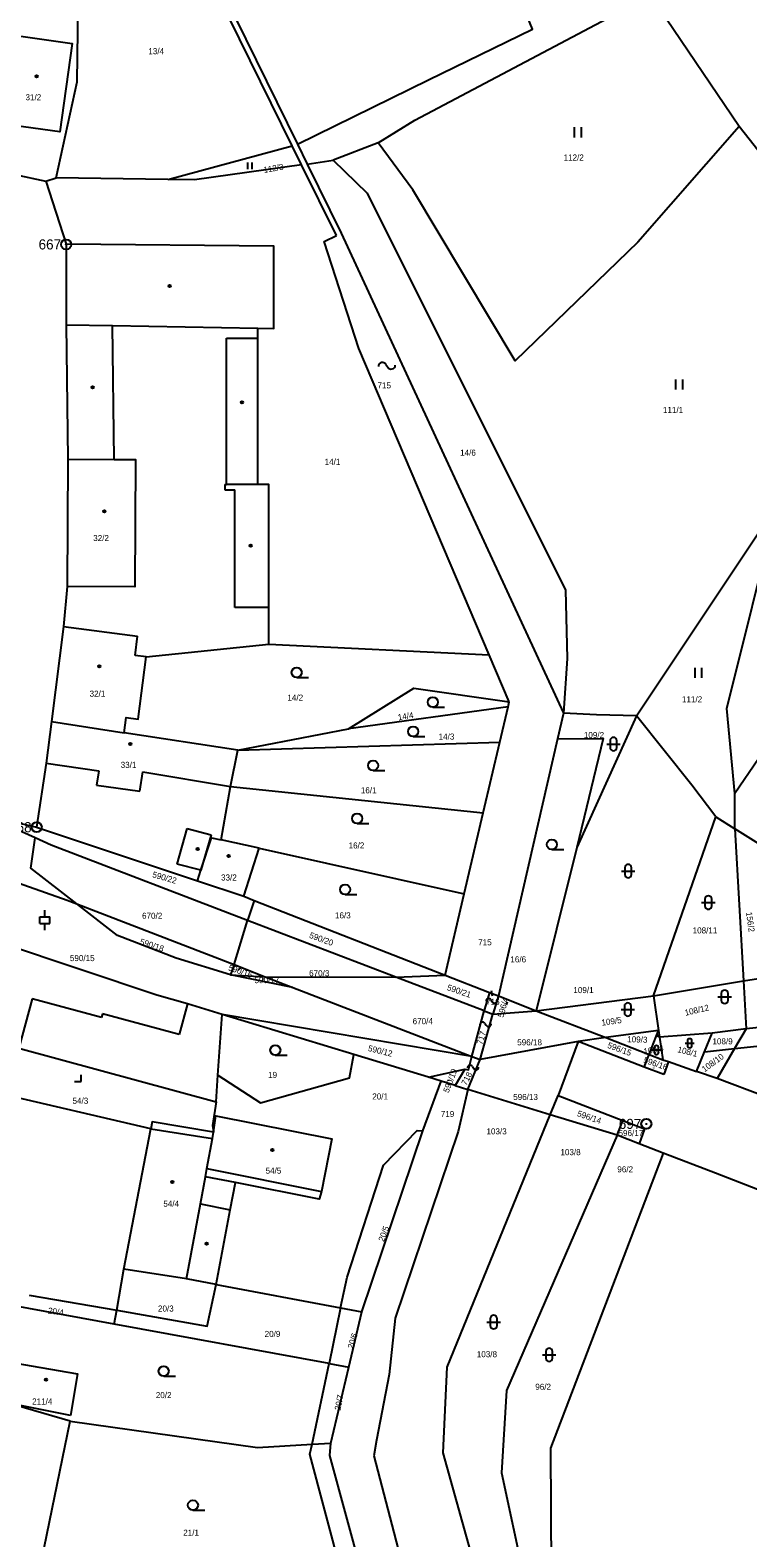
# Model space of a CAD drawing. Extents: x -758582 to -751794, y -998770 to -994350.
# Drawn here: x -755540.5 to -755433.6, y -995731.7 to -995507.3 of the extents above; entities that cross this region are included whole.
import ezdxf

# ---------------------------------------------------------------- set-up
doc = ezdxf.new("R2010")
doc.units = 0
for name, color, linetype in [('Hranice parcel', 7, 'Continuous'), ('Parcelní čísla', 7, 'Continuous'), ('Pop  PČ popisy', 7, 'Continuous'), ('Vnitřní kresba', 7, 'Continuous'), ('Značky bodu BP', 7, 'Continuous'), ('Značky budov', 7, 'Continuous'), ('Značky kultur', 7, 'Continuous')]:
    doc.layers.add(name, color=color, linetype=linetype)

msp = doc.modelspace()

# ---------------------------------------------------------------- linework, layer by layer
at = {"layer": 'Hranice parcel'}
for p, q in [((-755501.46, -995524.47), (-755518.41, -995490.01)), ((-755434.91, -995521.6), (-755447.94, -995502.32)), ((-755430.66, -995526.98), (-755434.91, -995521.6)), ((-755519.99, -995529.5), (-755501.46, -995524.47)), ((-755500.07, -995527.3), (-755501.46, -995524.47)), ((-755500.67, -995524.25), (-755499.23, -995527.18)), ((-755488.68, -995524.04), (-755495.36, -995526.63)), ((-755499.23, -995527.18), (-755495.36, -995526.63)), ((-755538.15, -995529.74), (-755536.58, -995529.23)), ((-755519.99, -995529.5), (-755536.58, -995529.23)), ((-755494.89, -995537.82), (-755500.07, -995527.3)), ((-755538.15, -995529.74), (-755535.12, -995539.1)), ((-755472.14, -995600.24), (-755491.55, -995554.63)), ((-755534.87, -995571.14), (-755534.97, -995590.08)), ((-755450.23, -995609.32), (-755429.18, -995577.78)), ((-755504.96, -995598.65), (-755472.14, -995600.24)), ((-755469.15, -995607.26), (-755472.14, -995600.24)), ((-755469.32, -995607.98), (-755469.15, -995607.26)), ((-755425.48, -995606.03), (-755435.57, -995620.9)), ((-755469.32, -995607.98), (-755493.08, -995611.28)), ((-755470.55, -995613.23), (-755469.32, -995607.98)), ((-755461.08, -995608.92), (-755461.96, -995612.75)), ((-755450.23, -995609.32), (-755459.08, -995628.93)), ((-755537.31, -995610.19), (-755526.49, -995611.85)), ((-755509.55, -995614.46), (-755526.49, -995611.85)), ((-755509.55, -995614.46), (-755493.08, -995611.28)), ((-755510.63, -995619.85), (-755509.55, -995614.46)), ((-755509.55, -995614.46), (-755470.55, -995613.23)), ((-755473.03, -995623.77), (-755470.55, -995613.23)), ((-755461.96, -995612.75), (-755470.78, -995651.03)), ((-755512.06, -995627.78), (-755510.63, -995619.85)), ((-755510.63, -995619.85), (-755473.03, -995623.77)), ((-755435.56, -995626.14), (-755435.57, -995620.9)), ((-755544.18, -995624.82), (-755539.51, -995625.91)), ((-755539.74, -995627.52), (-755543.7, -995625.72)), ((-755475.87, -995635.85), (-755473.03, -995623.77)), ((-755447.69, -995651.02), (-755438.4, -995624.35)), ((-755438.4, -995624.35), (-755435.56, -995626.14)), ((-755537.36, -995628.6), (-755539.74, -995627.52)), ((-755539.51, -995625.91), (-755515.56, -995633.91)), ((-755506.38, -995629.05), (-755512.06, -995627.78)), ((-755431.61, -995628.62), (-755435.56, -995626.14)), ((-755435.56, -995626.14), (-755434.3, -995648.77)), ((-755508.1, -995639.79), (-755537.36, -995628.6)), ((-755508.69, -995636.2), (-755506.38, -995629.05)), ((-755506.38, -995629.05), (-755475.87, -995635.85)), ((-755459.08, -995628.93), (-755465.13, -995653.23)), ((-755515.56, -995633.91), (-755508.69, -995636.2)), ((-755508.69, -995636.2), (-755507.13, -995636.81)), ((-755507.13, -995636.81), (-755508.1, -995639.79)), ((-755507.13, -995636.81), (-755478.71, -995647.93)), ((-755478.71, -995647.93), (-755475.87, -995635.85)), ((-755533.53, -995637.33), (-755510.13, -995646.37)), ((-755510.13, -995646.37), (-755508.1, -995639.79)), ((-755486.03, -995648.23), (-755508.1, -995639.79)), ((-755510.13, -995646.37), (-755510.66, -995647.89)), ((-755501.38, -995649.76), (-755510.66, -995647.89)), ((-755510.66, -995647.89), (-755505.48, -995648.17)), ((-755510.13, -995646.37), (-755505.48, -995648.17)), ((-755505.48, -995648.17), (-755486.03, -995648.23)), ((-755505.48, -995648.17), (-755501.38, -995649.76)), ((-755486.03, -995648.23), (-755478.71, -995647.93)), ((-755478.71, -995647.93), (-755472.12, -995650.51)), ((-755434.3, -995648.77), (-755426.44, -995647.6)), ((-755501.38, -995649.76), (-755474.71, -995660.06)), ((-755472.91, -995653.25), (-755486.03, -995648.23)), ((-755447.69, -995651.02), (-755434.3, -995648.77)), ((-755434.3, -995648.77), (-755433.9, -995655.95)), ((-755472.12, -995650.51), (-755470.78, -995651.03)), ((-755470.78, -995651.03), (-755471.61, -995653.75)), ((-755470.78, -995651.03), (-755465.13, -995653.23)), ((-755465.13, -995653.23), (-755447.69, -995651.02)), ((-755447.69, -995651.02), (-755446.93, -995656.16)), ((-755512.52, -995662.81), (-755511.87, -995653.79)), ((-755474.71, -995660.06), (-755511.87, -995653.79)), ((-755492.3, -995659.75), (-755511.87, -995653.79)), ((-755474.71, -995660.06), (-755472.91, -995653.25)), ((-755473.51, -995660.52), (-755471.61, -995653.75)), ((-755472.91, -995653.25), (-755471.61, -995653.75)), ((-755471.61, -995653.75), (-755465.13, -995653.23)), ((-755465.13, -995653.23), (-755454.79, -995657.23)), ((-755446.93, -995656.16), (-755454.79, -995657.23)), ((-755448.31, -995659.74), (-755446.93, -995656.16)), ((-755446.93, -995656.16), (-755446.78, -995657.19)), ((-755438.97, -995656.57), (-755446.78, -995657.19)), ((-755440.11, -995659.36), (-755438.97, -995656.57)), ((-755433.9, -995655.95), (-755438.97, -995656.57)), ((-755433.9, -995655.95), (-755435.62, -995658.88)), ((-755426.31, -995655.13), (-755433.9, -995655.95)), ((-755458.92, -995657.8), (-755473.51, -995660.52)), ((-755458.92, -995657.8), (-755461.9, -995665.86)), ((-755454.79, -995657.23), (-755458.92, -995657.8)), ((-755449.06, -995661.62), (-755458.92, -995657.8)), ((-755454.79, -995657.23), (-755448.31, -995659.74)), ((-755446.78, -995657.19), (-755446.28, -995660.53)), ((-755441.29, -995662.26), (-755440.11, -995659.36)), ((-755440.11, -995659.36), (-755435.62, -995658.88)), ((-755435.62, -995658.88), (-755438.23, -995663.32)), ((-755435.62, -995658.88), (-755427.59, -995658.02)), ((-755481.18, -995663.13), (-755492.3, -995659.75)), ((-755475.3, -995664.98), (-755473.51, -995660.52)), ((-755474.71, -995660.06), (-755473.51, -995660.52)), ((-755449.06, -995661.62), (-755448.31, -995659.74)), ((-755446.15, -995662.74), (-755449.06, -995661.62)), ((-755448.31, -995659.74), (-755446.28, -995660.53)), ((-755446.28, -995660.53), (-755445.47, -995660.81)), ((-755445.47, -995660.81), (-755446.15, -995662.74)), ((-755445.47, -995660.81), (-755441.29, -995662.26)), ((-755512.8, -995666.79), (-755512.52, -995662.81)), ((-755482.01, -995671.1), (-755479.31, -995663.72)), ((-755481.18, -995663.13), (-755475.78, -995661.92)), ((-755479.31, -995663.72), (-755481.18, -995663.13)), ((-755477.21, -995664.38), (-755479.31, -995663.72)), ((-755475.78, -995661.92), (-755477.21, -995664.38)), ((-755438.23, -995663.32), (-755441.29, -995662.26)), ((-755431.12, -995666), (-755438.23, -995663.32)), ((-755522.53, -995670.82), (-755550.45, -995664.32)), ((-755477.21, -995664.38), (-755475.3, -995664.98)), ((-755463.07, -995668.72), (-755475.3, -995664.98)), ((-755463.07, -995668.72), (-755461.9, -995665.86)), ((-755461.9, -995665.86), (-755452.23, -995669.59)), ((-755453.09, -995671.77), (-755463.07, -995668.72)), ((-755453.09, -995671.77), (-755452.23, -995669.59)), ((-755526.51, -995691.69), (-755522.53, -995670.82)), ((-755491.12, -995698.07), (-755482.01, -995671.1)), ((-755449.8, -995673.04), (-755453.09, -995671.77)), ((-755446.24, -995674.42), (-755449.8, -995673.04)), ((-755493.3, -995692.92), (-755487.9, -995676.22)), ((-755510.7, -995682.9), (-755509.93, -995678.82)), ((-755512.79, -995693.99), (-755510.7, -995682.9)), ((-755527.59, -995697.79), (-755526.51, -995691.69)), ((-755494.26, -995697.48), (-755493.3, -995692.92)), ((-755512.79, -995693.99), (-755494.26, -995697.48)), ((-755527.97, -995699.89), (-755547.25, -995696.36)), ((-755540.63, -995695.6), (-755527.59, -995697.79)), ((-755494.26, -995697.48), (-755495.99, -995705.74)), ((-755494.26, -995697.48), (-755491.12, -995698.07)), ((-755527.97, -995699.89), (-755527.59, -995697.79)), ((-755493.03, -995706.28), (-755491.12, -995698.07)), ((-755495.99, -995705.74), (-755527.97, -995699.89)), ((-755498.52, -995717.76), (-755495.99, -995705.74)), ((-755495.99, -995705.74), (-755493.03, -995706.28)), ((-755495.74, -995717.59), (-755493.03, -995706.28)), ((-755534.54, -995714.36), (-755543.92, -995711.63)), ((-755534.48, -995713.48), (-755543.92, -995711.63)), ((-755539.7, -995739.68), (-755534.54, -995714.36)), ((-755498.52, -995717.76), (-755495.74, -995717.59))]:
    msp.add_line(p, q, dxfattribs=at)
for points in [[(-755500.67, -995524.25), (-755481.17, -995514.65), (-755465.72, -995507.1), (-755477.43, -995478.45), (-755504.42, -995486.64)], [(-755516.07, -995489.69), (-755517.57, -995489.9), (-755500.67, -995524.25)], [(-755536.58, -995529.23), (-755533.47, -995514.96), (-755533.17, -995492.19)], [(-755488.68, -995524.04), (-755483.23, -995520.67), (-755454.56, -995505.52), (-755447.94, -995502.32)], [(-755542.58, -995508.06), (-755534.21, -995509.22), (-755536.04, -995522.4), (-755545.85, -995521.03), (-755544.4, -995510.63), (-755546.08, -995510.39), (-755545.83, -995508.61), (-755542.71, -995509.05), (-755542.58, -995508.06)], [(-755434.91, -995521.6), (-755450.04, -995538.83), (-755468.3, -995556.47), (-755483.49, -995531.04), (-755488.68, -995524.04)], [(-755560.21, -995523.57), (-755552.85, -995525.76), (-755542.78, -995528.76), (-755538.15, -995529.74)], [(-755495.36, -995526.63), (-755490.29, -995531.54), (-755460.76, -995590.63), (-755460.56, -995600.8), (-755461.08, -995608.92)], [(-755500.07, -995527.3), (-755516, -995529.56), (-755519.99, -995529.5)], [(-755499.23, -995527.18), (-755494.17, -995537.47), (-755461.08, -995608.92)], [(-755491.55, -995554.63), (-755496.69, -995538.71), (-755494.89, -995537.82)], [(-755535.12, -995539.1), (-755535.12, -995551.11), (-755534.87, -995571.14)], [(-755504.96, -995598.65), (-755504.96, -995593.2), (-755504.96, -995574.9), (-755506.56, -995574.9), (-755506.56, -995553.1), (-755506.56, -995551.63), (-755504.18, -995551.67), (-755504.19, -995539.4), (-755535.12, -995539.1)], [(-755534.87, -995571.14), (-755527.98, -995571.18), (-755524.8, -995571.19), (-755524.9, -995590.13), (-755534.97, -995590.08)], [(-755435.57, -995620.9), (-755436.79, -995608.25), (-755429.18, -995577.78)], [(-755534.97, -995590.08), (-755535.5, -995596.05), (-755537.31, -995610.19)], [(-755526.49, -995611.85), (-755526.19, -995609.59), (-755524.4, -995609.82), (-755523.22, -995600.54), (-755504.96, -995598.65)], [(-755493.08, -995611.28), (-755483.37, -995605.2), (-755469.15, -995607.26)], [(-755450.23, -995609.32), (-755456.19, -995609.2), (-755461.08, -995608.92)], [(-755438.4, -995624.35), (-755441.99, -995619.64), (-755450.23, -995609.32)], [(-755653.1, -995610.49), (-755646.26, -995612.32), (-755573.35, -995625.42), (-755559.76, -995628.44), (-755551.97, -995630.77), (-755534.97, -995636.78), (-755533.53, -995637.33)], [(-755537.31, -995610.19), (-755538.1, -995616.36), (-755539.51, -995625.91)], [(-755461.96, -995612.75), (-755455.2, -995612.71), (-755459.08, -995628.93)], [(-755533.53, -995637.33), (-755540.38, -995632.03), (-755539.74, -995627.52)], [(-755515.56, -995633.91), (-755515.05, -995632.33), (-755513.49, -995627.51), (-755512.06, -995627.78)], [(-755510.66, -995647.89), (-755518.75, -995645.43), (-755527.45, -995642.04), (-755533.53, -995637.33)], [(-755511.87, -995653.79), (-755517.07, -995652.21), (-755521.62, -995650.93), (-755544.6, -995643.22)], [(-755472.12, -995650.51), (-755472.85, -995653.01), (-755472.91, -995653.25)], [(-755548.51, -995657.09), (-755542.15, -995658.79), (-755512.8, -995666.79)], [(-755512.52, -995662.81), (-755506.19, -995666.96), (-755492.93, -995663.24), (-755492.3, -995659.75)], [(-755475.78, -995661.92), (-755475.23, -995662.04), (-755474.71, -995660.06)], [(-755475.3, -995664.98), (-755476.78, -995671.23), (-755486.16, -995699), (-755487.02, -995707.38), (-755488.91, -995717.17), (-755489.32, -995719.48)], [(-755512.8, -995666.79), (-755513.32, -995670.31), (-755513.16, -995671.3)], [(-755513.16, -995671.3), (-755522.33, -995669.76), (-755522.53, -995670.82)], [(-755513.16, -995671.3), (-755512.82, -995668.88), (-755495.58, -995672.33), (-755497.12, -995680.14), (-755497.43, -995681.29), (-755509.93, -995678.82)], [(-755468.42, -995763.84), (-755470.62, -995749.14), (-755478.99, -995719.07), (-755478.39, -995706.28), (-755463.07, -995668.72)], [(-755452.23, -995669.59), (-755449.02, -995670.83), (-755449.8, -995673.04)], [(-755514.16, -995676.73), (-755513.34, -995672.28), (-755513.16, -995671.3)], [(-755487.9, -995676.22), (-755482.85, -995671.08), (-755482.01, -995671.1)], [(-755453.09, -995671.77), (-755469.57, -995709.78), (-755470.33, -995722.02), (-755466.97, -995737.5)], [(-755446.24, -995674.42), (-755463.02, -995718.38), (-755462.93, -995736.73)], [(-755332.41, -995718.68), (-755438.45, -995677.43), (-755446.24, -995674.42)], [(-755509.93, -995678.82), (-755514.38, -995677.94), (-755514.16, -995676.73)], [(-755512.79, -995693.99), (-755517.19, -995693.17), (-755526.51, -995691.69)], [(-755527.59, -995697.79), (-755514.13, -995700.22), (-755512.79, -995693.99)], [(-755542.9, -995705.64), (-755533.45, -995707.3), (-755534.48, -995713.48)], [(-755534.54, -995714.36), (-755506.64, -995718.26), (-755498.52, -995717.76)], [(-755491.76, -995745.91), (-755498.83, -995719.23), (-755498.52, -995717.76)], [(-755488.58, -995746.23), (-755495.85, -995719.47), (-755495.74, -995717.59)], [(-755489.32, -995719.48), (-755477.02, -995766.71), (-755484.53, -995807.78), (-755498.8, -995841.6), (-755499.31, -995842.18)]]:
    msp.add_lwpolyline(points, dxfattribs=at)
at = {"layer": 'Pop  PČ popisy'}
for p, q in [((-755509.5, -995647.19), (-755509.22, -995646.9)), ((-755505.86, -995648.46), (-755505.82, -995648.58)), ((-755471.63, -995651.09), (-755471.78, -995650.26)), ((-755469.57, -995652.35), (-755469.4, -995651.9)), ((-755447.11, -995657.14), (-755446.79, -995656.68)), ((-755478.22, -995663.63), (-755478.22, -995663.69)), ((-755447.67, -995661.73), (-755447.7, -995661.78))]:
    msp.add_line(p, q, dxfattribs=at)
at = {"layer": 'Vnitřní kresba'}
for p, q in [((-755535.12, -995551.11), (-755528.23, -995551.24)), ((-755528.23, -995551.24), (-755506.56, -995551.63)), ((-755527.98, -995571.18), (-755528.23, -995551.24)), ((-755511.27, -995553.1), (-755506.56, -995553.1)), ((-755511.27, -995574.9), (-755511.27, -995553.1)), ((-755511.5, -995574.9), (-755511.5, -995575.7)), ((-755511.5, -995574.9), (-755511.27, -995574.9)), ((-755511.5, -995575.7), (-755510, -995575.7)), ((-755506.56, -995574.9), (-755511.27, -995574.9)), ((-755510, -995593.2), (-755510, -995575.7)), ((-755504.96, -995593.2), (-755510, -995593.2)), ((-755535.5, -995596.05), (-755524.49, -995597.46)), ((-755524.86, -995600.34), (-755524.49, -995597.46)), ((-755523.22, -995600.54), (-755524.86, -995600.34)), ((-755538.1, -995616.36), (-755530.27, -995617.5)), ((-755530.27, -995617.5), (-755530.6, -995619.63)), ((-755524.15, -995620.54), (-755523.68, -995617.65)), ((-755523.68, -995617.65), (-755510.63, -995619.85)), ((-755530.6, -995619.63), (-755524.15, -995620.54)), ((-755518.57, -995631.42), (-755517.1, -995626.09)), ((-755517.1, -995626.09), (-755513.55, -995627.04)), ((-755513.55, -995627.04), (-755515.05, -995632.33)), ((-755515.05, -995632.33), (-755518.57, -995631.42)), ((-755540.19, -995651.45), (-755542.15, -995658.79)), ((-755529.87, -995654.22), (-755540.19, -995651.45)), ((-755517.07, -995652.21), (-755518.28, -995656.75)), ((-755529.73, -995653.69), (-755529.87, -995654.22)), ((-755518.28, -995656.75), (-755529.73, -995653.69)), ((-755522.53, -995670.82), (-755513.34, -995672.28)), ((-755514.16, -995676.73), (-755497.12, -995680.14)), ((-755515.13, -995681.99), (-755514.38, -995677.94)), ((-755517.19, -995693.17), (-755515.13, -995681.99)), ((-755515.13, -995681.99), (-755510.7, -995682.9))]:
    msp.add_line(p, q, dxfattribs=at)
at = {"layer": 'Značky bodu BP'}
for centre, radius in [((-755535.12, -995539.15), 0.75), ((-755535.12, -995539.15), 0.03), ((-755539.51, -995625.91), 0.75), ((-755539.51, -995625.91), 0.03), ((-755448.75, -995670.08), 0.75), ((-755448.75, -995670.08), 0.03)]:
    msp.add_circle(centre, radius, dxfattribs=at)
at = {"layer": 'Značky budov'}
for p, q in [((-755487.53, -995557.01), (-755487.23, -995557.41)), ((-755471.88, -995651.63), (-755471.68, -995651.89)), ((-755472.78, -995655.13), (-755472.58, -995655.39)), ((-755474.65, -995661.56), (-755474.45, -995661.82))]:
    msp.add_line(p, q, dxfattribs=at)
for centre in [(-755539.51, -995514.12), (-755519.73, -995545.32), (-755531.19, -995560.45), (-755508.96, -995562.67), (-755529.41, -995578.9), (-755507.63, -995584.01), (-755530.19, -995601.94), (-755525.57, -995613.53), (-755515.53, -995629.14), (-755510.95, -995630.19), (-755504.42, -995673.95), (-755519.32, -995678.74), (-755514.21, -995687.91), (-755538.1, -995708.18)]:
    msp.add_circle(centre, 0.175, dxfattribs=at)
for centre, radius, start, end in [((-755488.04, -995557.3), 0.588, 29.2914, 181.2189), ((-755486.72, -995557.12), 0.588, 209.2914, 1.2189), ((-755472.22, -995651.82), 0.394, 29.2914, 181.2189), ((-755471.34, -995651.7), 0.394, 209.2914, 1.2189), ((-755473.12, -995655.32), 0.394, 29.2914, 181.2189), ((-755472.24, -995655.2), 0.394, 209.2914, 1.2189), ((-755474.99, -995661.75), 0.394, 29.2914, 181.2189), ((-755474.11, -995661.63), 0.394, 209.2914, 1.2189)]:
    msp.add_arc(centre, radius, start, end, dxfattribs=at)
at = {"layer": 'Značky kultur'}
for p, q in [((-755459.42, -995523.21), (-755459.42, -995521.71)), ((-755458.42, -995523.21), (-755458.42, -995521.71)), ((-755508.08, -995527.96), (-755508.08, -995526.96)), ((-755507.41, -995527.96), (-755507.41, -995526.96)), ((-755444.34, -995560.77), (-755444.34, -995559.27)), ((-755443.34, -995560.77), (-755443.34, -995559.27)), ((-755441.49, -995603.69), (-755441.49, -995602.19)), ((-755440.49, -995603.69), (-755440.49, -995602.19)), ((-755500.8, -995603.63), (-755499.05, -995603.63)), ((-755480.54, -995608.05), (-755478.79, -995608.05)), ((-755483.47, -995612.41), (-755481.72, -995612.41)), ((-755454.65, -995613.54), (-755452.65, -995613.54)), ((-755454.15, -995613.04), (-755454.15, -995614.04)), ((-755453.15, -995614.04), (-755453.15, -995613.04)), ((-755489.43, -995617.48), (-755487.68, -995617.48)), ((-755491.8, -995625.36), (-755490.05, -995625.36)), ((-755462.8, -995629.23), (-755461.05, -995629.23)), ((-755452.46, -995632.45), (-755450.46, -995632.45)), ((-755451.96, -995631.95), (-755451.96, -995632.95)), ((-755450.96, -995632.95), (-755450.96, -995631.95)), ((-755493.6, -995635.94), (-755491.85, -995635.94)), ((-755440.02, -995636.63), (-755440.02, -995637.63)), ((-755439.02, -995637.63), (-755439.02, -995636.63)), ((-755538.28, -995639.25), (-755538.28, -995638.25)), ((-755440.52, -995637.13), (-755438.52, -995637.13)), ((-755539.03, -995639.25), (-755537.53, -995639.25)), ((-755539.03, -995640.25), (-755539.03, -995639.25)), ((-755539.03, -995640.25), (-755537.53, -995640.25)), ((-755538.28, -995641.25), (-755538.28, -995640.25)), ((-755537.53, -995640.25), (-755537.53, -995639.25)), ((-755452.02, -995652.55), (-755452.02, -995653.55)), ((-755451.02, -995653.55), (-755451.02, -995652.55)), ((-755438.09, -995651.17), (-755436.09, -995651.17)), ((-755437.59, -995650.67), (-755437.59, -995651.67)), ((-755436.59, -995651.67), (-755436.59, -995650.67)), ((-755452.52, -995653.05), (-755450.52, -995653.05)), ((-755447.92, -995659.08), (-755446.58, -995659.08)), ((-755447.58, -995658.74), (-755447.58, -995659.42)), ((-755446.92, -995659.42), (-755446.92, -995658.74)), ((-755442.97, -995658.06), (-755441.63, -995658.06)), ((-755442.64, -995657.72), (-755442.64, -995658.4)), ((-755441.96, -995658.4), (-755441.96, -995657.72)), ((-755503.98, -995659.85), (-755502.23, -995659.85)), ((-755533.88, -995663.76), (-755532.88, -995663.76)), ((-755532.88, -995663.76), (-755532.88, -995662.76)), ((-755472.48, -995699.58), (-755470.48, -995699.58)), ((-755471.98, -995699.08), (-755471.98, -995700.08)), ((-755470.98, -995700.08), (-755470.98, -995699.08)), ((-755463.72, -995703.97), (-755463.72, -995704.97)), ((-755462.72, -995704.97), (-755462.72, -995703.97)), ((-755464.22, -995704.47), (-755462.22, -995704.47)), ((-755520.6, -995707.65), (-755518.85, -995707.65)), ((-755516.24, -995727.61), (-755514.49, -995727.61))]:
    msp.add_line(p, q, dxfattribs=at)
for centre in [(-755500.8, -995602.88), (-755480.54, -995607.3), (-755483.47, -995611.66), (-755489.43, -995616.73), (-755491.8, -995624.61), (-755462.8, -995628.48), (-755493.6, -995635.19), (-755503.98, -995659.1), (-755520.6, -995706.9), (-755516.24, -995726.86)]:
    msp.add_circle(centre, 0.75, dxfattribs=at)
for centre, radius, start, end in [((-755453.65, -995613.04), 0.5, 0, 180), ((-755453.65, -995614.04), 0.5, 180, 359.9879), ((-755451.46, -995631.95), 0.5, 0, 180), ((-755451.46, -995632.95), 0.5, 180, 359.9879), ((-755439.52, -995636.63), 0.5, 0, 180), ((-755439.52, -995637.63), 0.5, 180, 359.9879), ((-755437.09, -995650.67), 0.5, 0, 180), ((-755451.52, -995652.55), 0.5, 0, 180), ((-755437.09, -995651.67), 0.5, 180, 359.9879), ((-755451.52, -995653.55), 0.5, 180, 359.9879), ((-755447.25, -995658.75), 0.335, 0, 180), ((-755447.25, -995659.42), 0.335, 180, 359.9879), ((-755442.3, -995657.73), 0.335, 0, 180), ((-755442.3, -995658.4), 0.335, 180, 359.9879), ((-755471.48, -995699.08), 0.5, 0, 180), ((-755471.48, -995700.08), 0.5, 180, 359.9879), ((-755463.22, -995703.97), 0.5, 0, 180), ((-755463.22, -995704.97), 0.5, 180, 359.9879)]:
    msp.add_arc(centre, radius, start, end, dxfattribs=at)

# ---------------------------------------------------------------- texts
at = {"layer": 'Parcelní čísla'}
for s, p in [('13/4', (-755522.88, -995510.83)), ('31/2', (-755541.17, -995517.69)), ('112/2', (-755461.07, -995526.66)), ('715', (-755488.77, -995560.59)), ('111/1', (-755446.28, -995564.24)), ('14/1', (-755496.64, -995571.97)), ('14/6', (-755476.47, -995570.6)), ('32/2', (-755531.09, -995583.31)), ('32/1', (-755531.63, -995606.48)), ('14/2', (-755502.18, -995607.07)), ('111/2', (-755443.45, -995607.32)), ('14/3', (-755479.67, -995612.87)), ('109/2', (-755458.05, -995612.64)), ('33/1', (-755527, -995617.08)), ('16/1', (-755491.25, -995620.87)), ('16/2', (-755493.07, -995629.08)), ('33/2', (-755512.06, -995633.85)), ('670/2', (-755523.82, -995639.55)), ('16/3', (-755495.1, -995639.49)), ('108/11', (-755441.86, -995641.73)), ('715', (-755473.78, -995643.49)), ('590/15', (-755534.56, -995645.85)), ('16/6', (-755468.99, -995646.04)), ('590/17', (-755507.08, -995649.13)), ('670/3', (-755498.95, -995648.1)), ('109/1', (-755459.61, -995650.61)), ('716', (-755472.6, -995652.35)), ('670/4', (-755483.54, -995655.24)), ('596/18', (-755467.97, -995658.39)), ('108/9', (-755438.91, -995658.24)), ('19', (-755505.06, -995663.24)), ('54/3', (-755534.17, -995667.09)), ('20/1', (-755489.55, -995666.45)), ('596/13', (-755468.57, -995666.52)), ('719', (-755479.35, -995669.06)), ('103/3', (-755472.55, -995671.64)), ('596/17', (-755452.89, -995671.9)), ('103/8', (-755461.54, -995674.74)), ('54/5', (-755505.43, -995677.49)), ('96/2', (-755453.07, -995677.3)), ('54/4', (-755520.65, -995682.41)), ('20/3', (-755521.45, -995698.02)), ('20/9', (-755505.57, -995701.8)), ('103/8', (-755473.99, -995704.82)), ('96/2', (-755465.28, -995709.67)), ('211/4', (-755540.18, -995711.86)), ('20/2', (-755521.77, -995710.91)), ('21/1', (-755517.69, -995731.39))]:
    msp.add_text(s, height=0.9, dxfattribs=at).set_placement(p)
for s, rotation, p in [('112/3', 10, (-755505.66, -995528.52)), ('14/4', 9, (-755485.67, -995610.02)), ('590/22', 344, (-755522.36, -995633.34)), ('156/2', 278, (-755433.92, -995638.59)), ('590/18', 342, (-755524.24, -995643.33)), ('590/20', 340, (-755499.01, -995642.35)), ('590/16', 341, (-755511.06, -995647.18)), ('590/21', 341, (-755478.51, -995650.13)), ('596/4', 75, (-755470.03, -995654.32)), ('108/12', 13, (-755442.93, -995654)), ('109/5', 8, (-755455.36, -995655.47)), ('717', 73, (-755473.17, -995658.36)), ('109/3', 358, (-755451.61, -995657.91)), ('590/12', 346, (-755490.25, -995659.21)), ('596/15', 340, (-755454.63, -995658.73)), ('109/4', 9, (-755449.08, -995659.76)), ('108/1', 346, (-755444.18, -995659.4)), ('596/16', 342, (-755449.26, -995660.97)), ('108/10', 36, (-755440.09, -995662.42)), ('590/19', 69, (-755478.19, -995665.53)), ('718', 62, (-755475.56, -995664.44)), ('596/14', 341, (-755459.13, -995668.9)), ('20/5', 69, (-755487.84, -995687.69)), ('20/4', 352, (-755537.87, -995698.3)), ('20/6', 73, (-755492.39, -995703.63)), ('20/7', 79, (-755494.29, -995712.8))]:
    msp.add_text(s, height=0.9, rotation=rotation, dxfattribs=at).set_placement(p)
at = {"layer": 'Značky bodu BP'}
for s, p in [('667', (-755539.22, -995539.9)), ('668', (-755543.61, -995626.66)), ('697', (-755452.85, -995670.83))]:
    msp.add_text(s, height=1.5, dxfattribs=at).set_placement(p)

doc.saveas('drawing.dxf')
